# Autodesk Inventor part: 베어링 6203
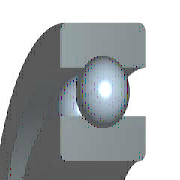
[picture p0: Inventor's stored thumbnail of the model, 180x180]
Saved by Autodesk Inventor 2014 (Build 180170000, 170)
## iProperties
IsCustomPart: 0
Created: 2014-10
Part Number: 베어링 6203
Material: 알루미늄 6061
Description: 깊은 그루브 볼 베어링
Document SubType Name: Modeling
Standard: KS B 2023
Designer: KYOUNG IL JANG
Standards Organization: KS
Language: ko-KR
Size Designation: 6203 - 17 x 40 x 12
Categories: <MemberInstance><Categories><Category DisplayName="샤프트 부품" InternalName="7f7aeb1f-a693-4053-b835-cee3144e0d98" Mnemonic="SHFT"><Category DisplayName="베어링" Inter
Density: 2.71 g/cm^3
Mass: 22.4044 g
Surface Area: 64.3582 cm^2
Volume: 8.26729 cm^3
Appearance: Aluminum - Flat
Author: SeoGD™ [www.esajin.kr]
Revision Number: 1
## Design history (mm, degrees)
sketch "스케치" dims "d0" = 5.98 (= -0.26 x WD + 0.26 x BD)
  geometry: L1 (3.01, 14.25)-(8.99, 14.25); L2 (6, 14.25)-(6, 11.26); L3 (6, 14.25)-(6, 17.24); L4 (3.778, 12.249)-(0, 12.249); L5 (0, 8.5)-(12, 8.5); L6 (3.778, 16.251)-(0, 16.251); L7 (0, 20)-(12, 20); L8 (12, 8.5)-(12, 12.249); L9 (8.222, 12.249)-(12, 12.249); L10 (8.222, 16.251)-(12, 16.251); L11 (12, 20)-(12, 16.251); L12 (-1.4, 0)-(8.4, 0) reference; L13 (0, -0.3)-(0, 5.3) reference
  constraints: 22 end point, 4 point on line, 2 collinear, 2 perpendicular, 2 symmetric about line, 1 midpoint, 1 parallel, 14 other
  dimensions: "d9" = 17 diameter of L5 L12 (= WD); "d11" = 40 diameter of L7 L12 (= BD); "d12" = 12 distance between parallel lines of L8 L13 (= KB); "d13" = 24.498 diameter of L9 L12 (= 0.326 x BD + 0.674 x WD)
revolve "본체" stored, may be unused: angle "d6" = 90 deg
revolve "볼" stored, may be unused: angle "d7" = 90 deg
pattern_circular "IDS_ARRAYBALL[SIMPL:T]" dims angle "d3" = 360 deg
body "Solid1"
fillet "모깎기1" dims "d1" = 0.6 (= KRS)
other parameters: "WD" = 17 [user parameter; used in 5 equation terms], "BD" = 40 [user parameter; used in 5 equation terms], "KB" = 12 [user parameter; used in 1 equation term], "KRS" = 0.6 [user parameter; used in 1 equation term], "d4" = 0, "d5" = 0, "d8" = 0, "d14" = 0, "d15" = 0, "BBA" = 0 [user parameter], "BC0" = 4750000 [user parameter], "BC" = 9560000 [user parameter], "WR" = 8.5 (= 0.5 x WD) [user parameter]
